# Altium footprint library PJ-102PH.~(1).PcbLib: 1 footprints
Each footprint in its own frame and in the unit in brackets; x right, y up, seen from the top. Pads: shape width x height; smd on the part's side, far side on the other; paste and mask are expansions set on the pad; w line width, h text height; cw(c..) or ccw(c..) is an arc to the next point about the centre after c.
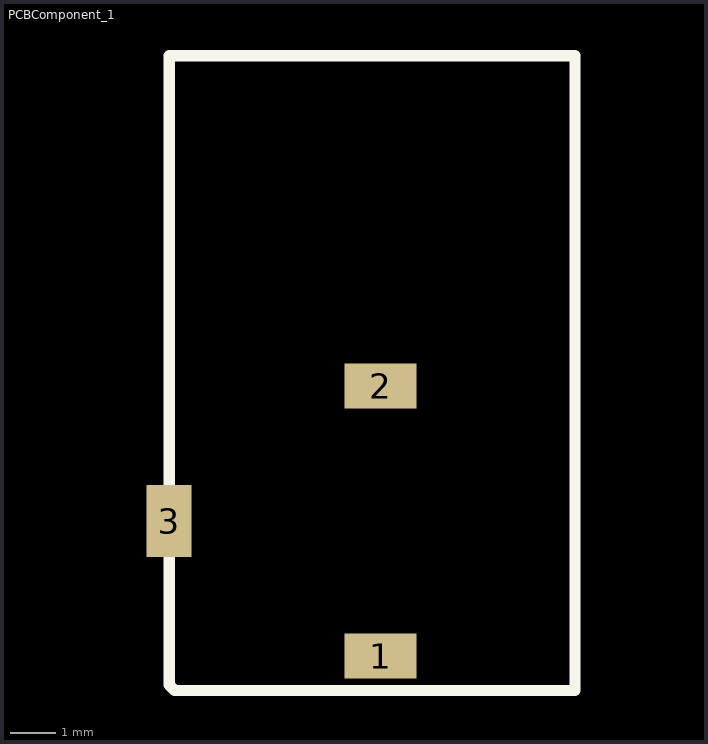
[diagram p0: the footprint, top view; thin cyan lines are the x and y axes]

## PCBComponent_1 [mm]
pads (3):
  rect 1.6x1 all layers, no hole: 1(-560.07,-803.783) 2(-560.07,-797.783)
  rect 1x1.6 all layers, no hole: 3(-564.77,-800.783)
Top Overlay:
  lines w0.254: -564.769,-804.418 -564.642,-804.545 -555.752,-804.545 -555.752,-790.448 -564.769,-790.448 -564.769,-804.418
